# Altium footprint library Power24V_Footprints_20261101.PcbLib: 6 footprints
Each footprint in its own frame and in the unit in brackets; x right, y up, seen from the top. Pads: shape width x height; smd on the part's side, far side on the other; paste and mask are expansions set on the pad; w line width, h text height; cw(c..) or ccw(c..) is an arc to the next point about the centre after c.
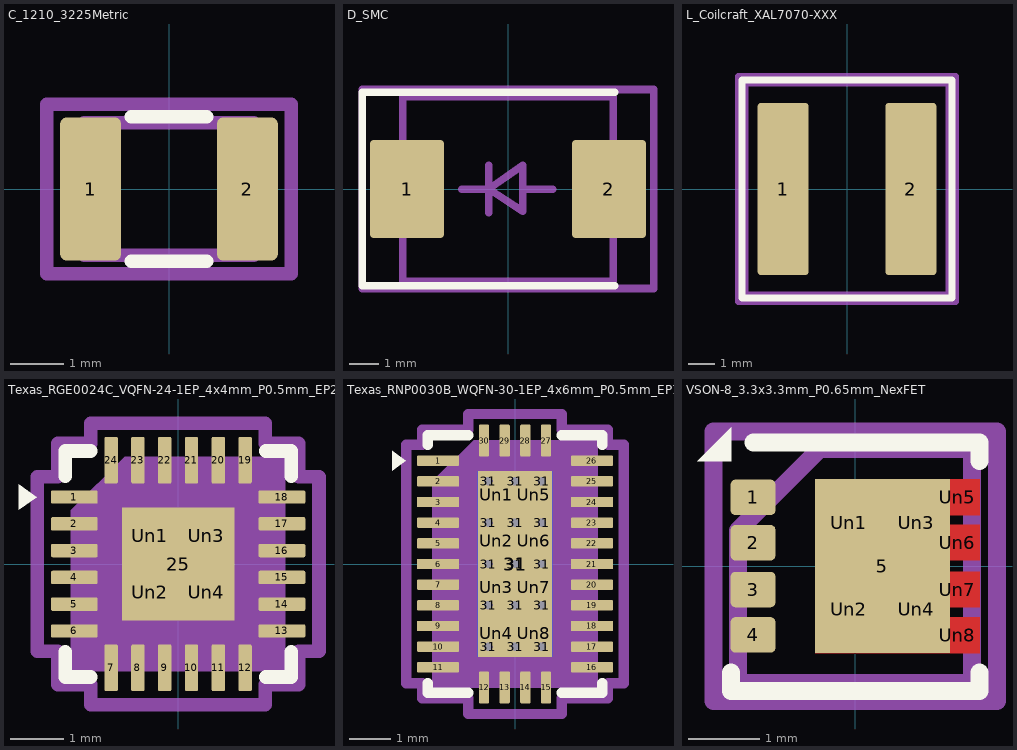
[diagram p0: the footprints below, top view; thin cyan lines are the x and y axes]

## C_1210_3225Metric [mm]
pads (2):
  rrect22% 1.15x2.7 smd mask+0: 1(-1.475,0) 2(1.475,0)
Top Overlay:
  lines w0.254: -0.711,-1.36 0.711,-1.36 ; -0.711,1.36 0.711,1.36
Mechanical 4:
  lines w0.254: -2.3,-1.6 -2.3,1.6 2.3,1.6 2.3,-1.6 -2.3,-1.6
Mechanical 6:
  lines w0.254: -1.6,-1.25 -1.6,1.25 1.6,1.25 1.6,-1.25 -1.6,-1.25
  text "'.Designator'" at -1.546,-0.52 h0.8

## D_SMC [mm]
pads (2):
  rrect10% 2.5x3.3 smd mask+0: 1(-3.4,0) 2(3.4,0)
Top Overlay:
  lines w0.254: 3.6,-3.25 -4.91,-3.25 -4.91,3.25 3.6,3.25
Mechanical 4:
  lines w0.254: -4.9,-3.35 4.9,-3.35 4.9,3.35 -4.9,3.35 -4.9,-3.35
Mechanical 6:
  lines w0.254: -1.551,-0.001 -0.649,-0.001 ; -0.649,-0.801 -0.649,0.799 ; 0.501,-0.001 1.499,-0.001 ; -0.649,-0.001 0.501,-0.75 0.501,0.799 -0.649,-0.001 ; -3.55,-3.1 3.55,-3.1 3.55,3.1 -3.55,3.1 -3.55,-3.1
  text "'.Designator'" at -1.933,1.25 h1

## L_Coilcraft_XAL7070-XXX [mm]
pads (2):
  rrect13% 1.92x6.5 smd mask+0: 1(-2.41,0) 2(2.41,0)
Top Overlay:
  lines w0.254: -3.96,-4.11 -3.96,4.11 3.96,4.11 3.96,-4.11 -3.96,-4.11
Mechanical 4:
  lines w0.254: -4.1,-4.25 -4.1,4.25 4.1,4.25 4.1,-4.25 -4.1,-4.25
Mechanical 6:
  lines w0.254: -3.85,-4 -3.85,4 3.85,4 3.85,-4 -3.85,-4
  text "'.Designator'" at -1.933,-0.65 h1

## Texas_RGE0024C_VQFN-24-1EP_4x4mm_P0.5mm_EP2.1x2.1mm [mm]
pads (29):
  rrect25% 0.875x0.25 smd mask+0: 1(-1.937,1.25) 2(-1.937,0.75) 3(-1.937,0.25) 4(-1.937,-0.25) 5(-1.937,-0.75) 6(-1.937,-1.25) 13(1.937,-1.25) 14(1.937,-0.75) 15(1.937,-0.25) 16(1.937,0.25) 17(1.937,0.75) 18(1.937,1.25)
  rrect25% 0.25x0.875 smd mask+0: 7(-1.25,-1.937) 8(-0.75,-1.937) 9(-0.25,-1.937) 10(0.25,-1.937) 11(0.75,-1.937) 12(1.25,-1.937) 19(1.25,1.937) 20(0.75,1.937) 21(0.25,1.937) 22(-0.25,1.937) 23(-0.75,1.937) 24(-1.25,1.937)
  rect 2.1x2.1 smd paste-2.1 mask+0: 25(0,0)
  rrect50% 0.85x0.85 on Top Paste mask-0.85: Un1(-0.525,0.525) Un2(-0.525,-0.525) Un3(0.525,0.525) Un4(0.525,-0.525)
Top Overlay:
  region: -2.64,1.25 -2.97,1.01 -2.97,1.49
  lines w0.254: -2.11,-1.635 -2.11,-2.11 -1.635,-2.11 ; -2.11,1.635 -2.11,2.11 -1.635,2.11 ; 1.635,-2.11 2.11,-2.11 2.11,-1.635 ; 1.635,2.11 2.11,2.11 2.11,1.635
Mechanical 4:
  lines w0.254: -2.63,-1.63 -2.63,1.63 -2.25,1.63 -2.25,2.25 -1.63,2.25 -1.63,2.63 1.63,2.63 1.63,2.25 2.25,2.25 2.25,1.63 2.63,1.63 2.63,-1.63 2.25,-1.63 2.25,-2.25 1.63,-2.25 1.63,-2.63 -1.63,-2.63 -1.63,-2.25 -2.25,-2.25 -2.25,-1.63 -2.63,-1.63
Mechanical 6:
  region: 2,-2 -2,-2 -2,1 -1,2 2,2
  text "'.Designator'" at -1.933,-0.65 h1

## Texas_RNP0030B_WQFN-30-1EP_4x6mm_P0.5mm_EP1.8x4.5mm_ThermalVias [mm]
pads (55):
  rrect25% 1.025x0.25 smd mask+0: 1(-1.863,2.5) 2(-1.863,2) 3(-1.863,1.5) 4(-1.863,1) 5(-1.863,0.5) 6(-1.863,0) 7(-1.863,-0.5) 8(-1.863,-1) 9(-1.863,-1.5) 10(-1.863,-2) 11(-1.863,-2.5) 16(1.863,-2.5) 17(1.863,-2) 18(1.863,-1.5) 19(1.863,-1) 20(1.863,-0.5) 21(1.863,0) 22(1.863,0.5) 23(1.863,1) 24(1.863,1.5) 25(1.863,2) 26(1.863,2.5)
  rrect25% 0.25x0.775 smd mask+0: 12(-0.75,-2.987) 13(-0.25,-2.987) 14(0.25,-2.987) 15(0.75,-2.987) 27(0.75,2.987) 28(0.25,2.987) 29(-0.25,2.987) 30(-0.75,2.987)
  round 0.5 hole 0.2 paste-2539.97 mask-0.5: 31(-0.65,-2) 31(-0.65,-1) 31(-0.65,0) 31(-0.65,1) 31(-0.65,2) 31(0,-2) 31(0,-1) 31(0,0) 31(0,1) 31(0,2) 31(0.65,-2) 31(0.65,-1) 31(0.65,0) 31(0.65,1) 31(0.65,2)
  rect 1.8x4.5 smd paste-4.5 mask+0: 31(0,0)
  rect 1.8x4.5 smd far side paste-4.5 mask-4.5: 31(0,0)
  rrect50% 0.78x0.97 on Top Paste mask-0.97: Un1(-0.45,1.68) Un2(-0.45,0.56) Un3(-0.45,-0.56) Un4(-0.45,-1.68) Un5(0.45,1.68) Un6(0.45,0.56) Un7(0.45,-0.56) Un8(0.45,-1.68)
Top Overlay:
  region: -2.64,2.5 -2.97,2.26 -2.97,2.74
  lines w0.254: -2.11,-2.885 -2.11,-3.11 -1.135,-3.11 ; -2.11,2.885 -2.11,3.11 -1.135,3.11 ; 1.135,-3.11 2.11,-3.11 2.11,-2.885 ; 1.135,3.11 2.11,3.11 2.11,2.885
Mechanical 4:
  lines w0.254: -2.63,-2.88 -2.63,2.88 -2.25,2.88 -2.25,3.25 -1.13,3.25 -1.13,3.63 1.13,3.63 1.13,3.25 2.25,3.25 2.25,2.88 2.63,2.88 2.63,-2.88 2.25,-2.88 2.25,-3.25 1.13,-3.25 1.13,-3.63 -1.13,-3.63 -1.13,-3.25 -2.25,-3.25 -2.25,-2.88 -2.63,-2.88
Mechanical 6:
  region: 2,-3 -2,-3 -2,2 -1,3 2,3
  text "'.Designator'" at -1.933,-0.65 h1

## VSON-8_3.3x3.3mm_P0.65mm_NexFET [mm]
pads (13):
  rrect25% 0.63x0.5 smd mask+0: 1(-1.44,0.97) 2(-1.44,0.33) 3(-1.44,-0.33) 4(-1.44,-0.97)
  rect 1.9x2.45 smd paste-2.45 mask+0: 5(0.385,0)
  rect 0.57x0.738 on Top Paste mask-0.738: Un1(-0.09,0.61) Un2(-0.09,-0.61) Un3(0.86,0.61) Un4(0.86,-0.61)
  rrect50% 0.63x0.5 on Top Paste mask-0.63: Un5(1.44,0.972) Un6(1.44,0.33) Un7(1.44,-0.33) Un8(1.44,-0.972)
Top Layer:
  region: 1.756,0.72 1.335,0.72 1.335,0.58 1.755,0.58 1.755,0.08 1.335,0.08 1.335,-0.08 1.755,-0.08 1.755,-0.58 1.335,-0.58 1.335,-0.72 1.755,-0.72 1.755,-1.225 -0.565,-1.225 -0.565,1.225 1.756,1.225
Top Overlay:
  region: -1.75,1.48 -2.23,1.48 -1.75,1.96
  lines w0.254: -1.75,-1.5 -1.75,-1.76 1.75,-1.76 1.75,-1.5 ; -1.43,1.74 1.75,1.74 1.75,1.48
Top Solder:
  region: 1.756,0.72 1.335,0.72 1.335,0.58 1.755,0.58 1.755,0.08 1.335,0.08 1.335,-0.08 1.755,-0.08 1.755,-0.58 1.335,-0.58 1.335,-0.72 1.755,-0.72 1.755,-1.225 -0.565,-1.225 -0.565,1.225 1.756,1.225
Mechanical 4:
  lines w0.254: -2,-1.9 -2,1.9 2,1.9 2,-1.9 -2,-1.9
Mechanical 6:
  lines w0.254: -1.65,-1.65 -1.65,0.5 -0.5,1.65 1.65,1.65 1.65,-1.65 -1.65,-1.65
  text "'.Designator'" at -0.822,-0.692 h0.7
